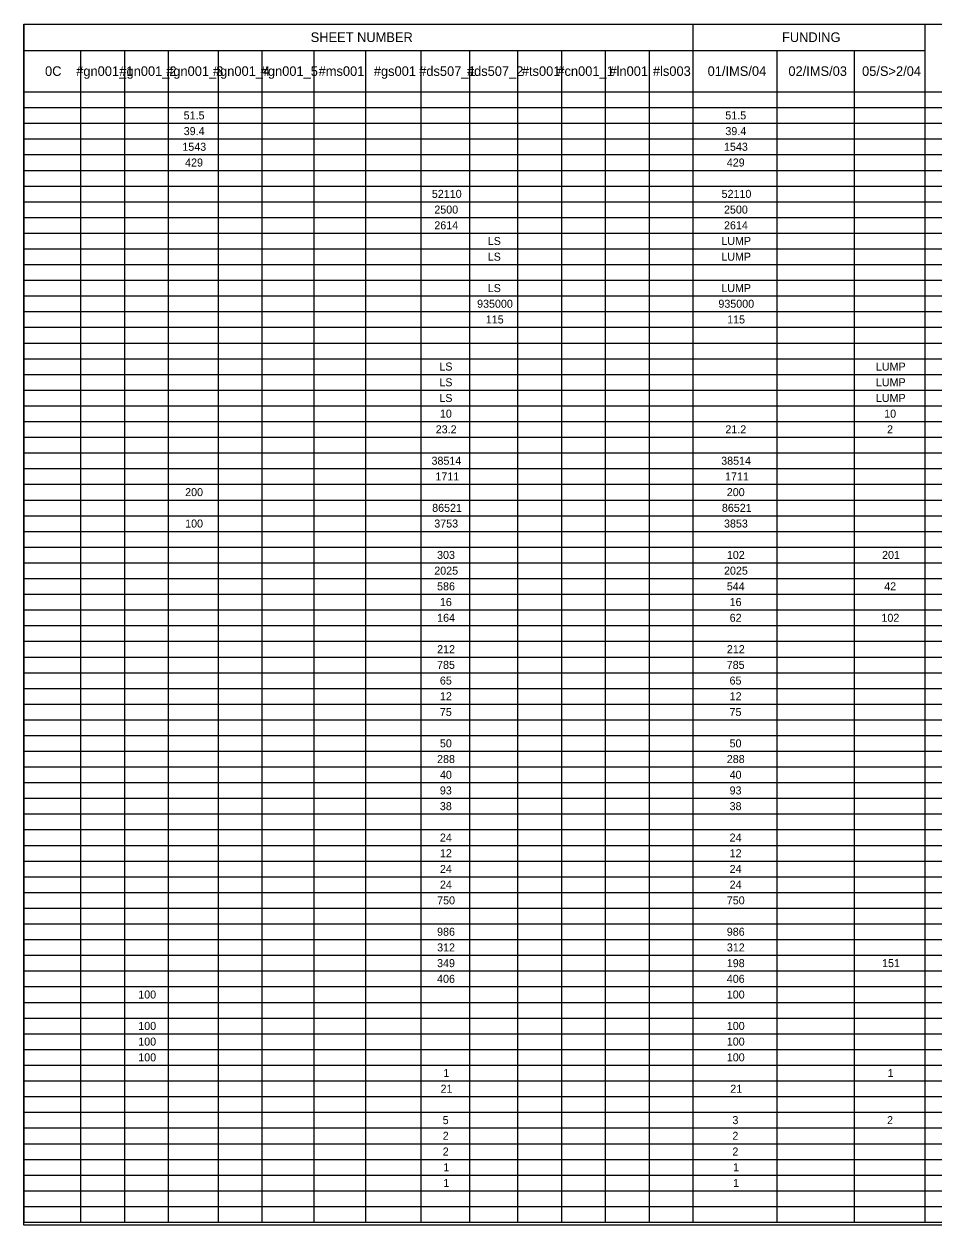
# Model space of a CAD drawing. Extents: x -542 to 295, y -281 to 32.
# Drawn here: x -416.36 to -400.45, y -40.59 to -19.59 of the extents above; entities that cross this region are included whole.
import ezdxf

# ---------------------------------------------------------------- set-up
doc = ezdxf.new("R2010")
doc.units = 0
for name, color, linetype in [('SC_Scratch1', 7, 'Continuous'), ('SH_Data', 7, 'Continuous'), ('SH_Text', 7, 'Continuous')]:
    doc.layers.add(name, color=color, linetype=linetype)

msp = doc.modelspace()

# ---------------------------------------------------------------- linework, layer by layer
at = {"layer": 'SC_Scratch1'}
msp.add_lwpolyline([(-416.359, -19.593), (-385.859, -19.593), (-385.859, -40.593), (-416.359, -40.593)], close=True, dxfattribs=at)
at = {"layer": 'SH_Data'}
for p, q in [((-416.359, -19.593), (-385.859, -19.593)), ((-416.359, -19.593), (-416.359, -40.543)), ((-404.663, -19.593), (-404.663, -40.543)), ((-400.608, -19.593), (-400.608, -40.543)), ((-416.359, -20.054), (-400.608, -20.054)), ((-415.369, -20.054), (-415.369, -40.543)), ((-414.603, -20.054), (-414.603, -40.543)), ((-413.836, -20.054), (-413.836, -40.543)), ((-412.964, -20.054), (-412.964, -40.543)), ((-412.198, -20.054), (-412.198, -40.543)), ((-411.293, -20.054), (-411.293, -40.543)), ((-410.388, -20.054), (-410.388, -40.543)), ((-409.42, -20.054), (-409.42, -40.543)), ((-408.569, -20.054), (-408.569, -40.543)), ((-407.728, -20.054), (-407.728, -40.543)), ((-406.962, -20.054), (-406.962, -40.543)), ((-406.195, -20.054), (-406.195, -40.543)), ((-405.429, -20.054), (-405.429, -40.543)), ((-403.194, -20.054), (-403.194, -40.543)), ((-401.843, -20.054), (-401.843, -40.543)), ((-416.359, -20.778), (-385.859, -20.778)), ((-416.359, -21.053), (-385.859, -21.053)), ((-416.359, -21.327), (-385.859, -21.327)), ((-416.359, -21.602), (-385.859, -21.602)), ((-416.359, -21.876), (-385.859, -21.876)), ((-416.359, -22.151), (-385.859, -22.151)), ((-416.359, -22.425), (-385.859, -22.425)), ((-416.359, -22.7), (-385.859, -22.7)), ((-416.359, -22.975), (-385.859, -22.975)), ((-416.359, -23.249), (-385.859, -23.249)), ((-416.359, -23.524), (-385.859, -23.524)), ((-416.359, -23.798), (-385.859, -23.798)), ((-416.359, -24.073), (-385.859, -24.073)), ((-416.359, -24.347), (-385.859, -24.347)), ((-416.359, -24.622), (-385.859, -24.622)), ((-416.359, -24.896), (-385.859, -24.896)), ((-416.359, -25.171), (-385.859, -25.171)), ((-416.359, -25.445), (-385.859, -25.445)), ((-416.359, -25.72), (-385.859, -25.72)), ((-416.359, -25.994), (-385.859, -25.994)), ((-416.359, -26.269), (-385.859, -26.269)), ((-416.359, -26.543), (-385.859, -26.543)), ((-416.359, -26.818), (-385.859, -26.818)), ((-416.359, -27.092), (-385.859, -27.092)), ((-416.359, -27.367), (-385.859, -27.367)), ((-416.359, -27.641), (-385.859, -27.641)), ((-416.359, -27.916), (-385.859, -27.916)), ((-416.359, -28.19), (-385.859, -28.19)), ((-416.359, -28.465), (-385.859, -28.465)), ((-416.359, -28.739), (-385.859, -28.739)), ((-416.359, -29.014), (-385.859, -29.014)), ((-416.359, -29.288), (-385.859, -29.288)), ((-416.359, -29.563), (-385.859, -29.563)), ((-416.359, -29.837), (-385.859, -29.837)), ((-416.359, -30.112), (-385.859, -30.112)), ((-416.359, -30.386), (-385.859, -30.386)), ((-416.359, -30.661), (-385.859, -30.661)), ((-416.359, -30.935), (-385.859, -30.935)), ((-416.359, -31.21), (-385.859, -31.21)), ((-416.359, -31.484), (-385.859, -31.484)), ((-416.359, -31.759), (-385.859, -31.759)), ((-416.359, -32.033), (-385.859, -32.033)), ((-416.359, -32.308), (-385.859, -32.308)), ((-416.359, -32.582), (-385.859, -32.582)), ((-416.359, -32.857), (-385.859, -32.857)), ((-416.359, -33.131), (-385.859, -33.131)), ((-416.359, -33.406), (-385.859, -33.406)), ((-416.359, -33.68), (-385.859, -33.68)), ((-416.359, -33.955), (-385.859, -33.955)), ((-416.359, -34.229), (-385.859, -34.229)), ((-416.359, -34.504), (-385.859, -34.504)), ((-416.359, -34.778), (-385.859, -34.778)), ((-416.359, -35.053), (-385.859, -35.053)), ((-416.359, -35.327), (-385.859, -35.327)), ((-416.359, -35.602), (-385.859, -35.602)), ((-416.359, -35.876), (-385.859, -35.876)), ((-416.359, -36.151), (-385.859, -36.151)), ((-416.359, -36.425), (-385.859, -36.425)), ((-416.359, -36.7), (-385.859, -36.7)), ((-416.359, -36.975), (-385.859, -36.975)), ((-416.359, -37.249), (-385.859, -37.249)), ((-416.359, -37.524), (-385.859, -37.524)), ((-416.359, -37.798), (-385.859, -37.798)), ((-416.359, -38.073), (-385.859, -38.073)), ((-416.359, -38.347), (-385.859, -38.347)), ((-416.359, -38.622), (-385.859, -38.622)), ((-416.359, -38.896), (-385.859, -38.896)), ((-416.359, -39.171), (-385.859, -39.171)), ((-416.359, -39.445), (-385.859, -39.445)), ((-416.359, -39.72), (-385.859, -39.72)), ((-416.359, -39.994), (-385.859, -39.994)), ((-416.359, -40.269), (-385.859, -40.269)), ((-416.359, -40.543), (-385.859, -40.543))]:
    msp.add_line(p, q, dxfattribs=at)

# ---------------------------------------------------------------- texts
at = {"layer": 'SH_Text'}
for s, height, p in [('SHEET NUMBER', 0.168, (-411.346, -19.907)), ('FUNDING', 0.168, (-403.105, -19.907)), ('0C', 0.168, (-415.991, -20.5)), ('#gn001_1', 0.168, (-415.446, -20.5)), ('#gn001_2', 0.168, (-414.691, -20.5)), ('#gn001_3', 0.168, (-413.873, -20.5)), ('#gn001_4', 0.168, (-413.055, -20.5)), ('#gn001_5', 0.168, (-412.219, -20.5)), ('#ms001', 0.168, (-411.207, -20.5)), ('#gs001', 0.168, (-410.242, -20.5)), ('#ds507_1', 0.168, (-409.449, -20.5)), ('#ds507_2', 0.168, (-408.614, -20.5)), ('#ts001', 0.168, (-407.654, -20.5)), ('#cn001_1', 0.168, (-407.033, -20.5)), ('#ln001', 0.168, (-406.122, -20.5)), ('#ls003', 0.168, (-405.362, -20.5)), ('01/IMS/04', 0.168, (-404.405, -20.5)), ('02/IMS/03', 0.168, (-402.993, -20.5)), ('05/S>2/04', 0.168, (-401.705, -20.5)), ('51.5', 0.14, (-413.567, -21.26)), ('51.5', 0.14, (-404.096, -21.26)), ('39.4', 0.14, (-413.566, -21.535)), ('39.4', 0.14, (-404.095, -21.535)), ('1543', 0.14, (-413.59, -21.809)), ('1543', 0.14, (-404.119, -21.809)), ('429', 0.14, (-413.542, -22.084)), ('429', 0.14, (-404.07, -22.084)), ('52110', 0.14, (-409.227, -22.633)), ('52110', 0.14, (-404.161, -22.633)), ('2500', 0.14, (-409.184, -22.907)), ('2500', 0.14, (-404.119, -22.907)), ('2614', 0.14, (-409.184, -23.182)), ('2614', 0.14, (-404.119, -23.182)), ('LS', 0.14, (-408.25, -23.456)), ('LUMP', 0.14, (-404.166, -23.456)), ('LS', 0.14, (-408.25, -23.731)), ('LUMP', 0.14, (-404.166, -23.731)), ('LS', 0.14, (-408.25, -24.28)), ('LUMP', 0.14, (-404.166, -24.28)), ('935000', 0.14, (-408.436, -24.554)), ('935000', 0.14, (-404.217, -24.554)), ('115', 0.14, (-408.284, -24.829)), ('115', 0.14, (-404.064, -24.829)), ('LS', 0.14, (-409.096, -25.652)), ('LUMP', 0.14, (-401.463, -25.652)), ('LS', 0.14, (-409.096, -25.927)), ('LUMP', 0.14, (-401.463, -25.927)), ('LS', 0.14, (-409.096, -26.201)), ('LUMP', 0.14, (-401.463, -26.201)), ('10', 0.14, (-409.086, -26.476)), ('10', 0.14, (-401.318, -26.476)), ('23.2', 0.14, (-409.16, -26.75)), ('21.2', 0.14, (-404.095, -26.75)), ('2', 0.14, (-401.268, -26.75)), ('38514', 0.14, (-409.233, -27.299)), ('38514', 0.14, (-404.168, -27.299)), ('1711', 0.14, (-409.166, -27.574)), ('1711', 0.14, (-404.101, -27.574)), ('200', 0.14, (-413.541, -27.848)), ('200', 0.14, (-404.07, -27.848)), ('86521', 0.14, (-409.222, -28.123)), ('86521', 0.14, (-404.156, -28.123)), ('100', 0.14, (-413.541, -28.397)), ('3753', 0.14, (-409.185, -28.397)), ('3853', 0.14, (-404.119, -28.397)), ('303', 0.14, (-409.136, -28.946)), ('102', 0.14, (-404.069, -28.946)), ('201', 0.14, (-401.355, -28.946)), ('2025', 0.14, (-409.185, -29.221)), ('2025', 0.14, (-404.119, -29.221)), ('586', 0.14, (-409.136, -29.495)), ('544', 0.14, (-404.07, -29.495)), ('42', 0.14, (-401.317, -29.495)), ('16', 0.14, (-409.087, -29.77)), ('16', 0.14, (-404.021, -29.77)), ('164', 0.14, (-409.135, -30.045)), ('62', 0.14, (-404.02, -30.045)), ('102', 0.14, (-401.366, -30.045)), ('212', 0.14, (-409.135, -30.594)), ('212', 0.14, (-404.069, -30.594)), ('785', 0.14, (-409.136, -30.868)), ('785', 0.14, (-404.071, -30.868)), ('65', 0.14, (-409.087, -31.143)), ('65', 0.14, (-404.022, -31.143)), ('12', 0.14, (-409.086, -31.417)), ('12', 0.14, (-404.02, -31.417)), ('75', 0.14, (-409.087, -31.692)), ('75', 0.14, (-404.022, -31.692)), ('50', 0.14, (-409.086, -32.241)), ('50', 0.14, (-404.021, -32.241)), ('288', 0.14, (-409.136, -32.515)), ('288', 0.14, (-404.07, -32.515)), ('40', 0.14, (-409.086, -32.79)), ('40', 0.14, (-404.021, -32.79)), ('93', 0.14, (-409.087, -33.064)), ('93', 0.14, (-404.021, -33.064)), ('38', 0.14, (-409.087, -33.339)), ('38', 0.14, (-404.021, -33.339)), ('24', 0.14, (-409.086, -33.888)), ('24', 0.14, (-404.021, -33.888)), ('12', 0.14, (-409.086, -34.162)), ('12', 0.14, (-404.02, -34.162)), ('24', 0.14, (-409.086, -34.437)), ('24', 0.14, (-404.021, -34.437)), ('24', 0.14, (-409.086, -34.711)), ('24', 0.14, (-404.021, -34.711)), ('750', 0.14, (-409.135, -34.986)), ('750', 0.14, (-404.07, -34.986)), ('986', 0.14, (-409.136, -35.535)), ('986', 0.14, (-404.07, -35.535)), ('312', 0.14, (-409.135, -35.809)), ('312', 0.14, (-404.069, -35.809)), ('349', 0.14, (-409.136, -36.084)), ('198', 0.14, (-404.07, -36.084)), ('151', 0.14, (-401.355, -36.084)), ('406', 0.14, (-409.136, -36.358)), ('406', 0.14, (-404.07, -36.358)), ('100', 0.14, (-414.361, -36.633)), ('100', 0.14, (-404.07, -36.633)), ('100', 0.14, (-414.361, -37.182)), ('100', 0.14, (-404.07, -37.182)), ('100', 0.14, (-414.361, -37.456)), ('100', 0.14, (-404.07, -37.456)), ('100', 0.14, (-414.361, -37.731)), ('100', 0.14, (-404.07, -37.731)), ('1', 0.14, (-409.026, -38.005)), ('1', 0.14, (-401.257, -38.005)), ('21', 0.14, (-409.075, -38.28)), ('21', 0.14, (-404.009, -38.28)), ('5', 0.14, (-409.038, -38.829)), ('3', 0.14, (-403.972, -38.829)), ('2', 0.14, (-401.268, -38.829)), ('2', 0.14, (-409.037, -39.103)), ('2', 0.14, (-403.972, -39.103)), ('2', 0.14, (-409.037, -39.378)), ('2', 0.14, (-403.972, -39.378)), ('1', 0.14, (-409.026, -39.652)), ('1', 0.14, (-403.96, -39.652)), ('1', 0.14, (-409.026, -39.927)), ('1', 0.14, (-403.96, -39.927))]:
    msp.add_text(s, height=height, dxfattribs=at).set_placement(p)

doc.saveas('drawing.dxf')
